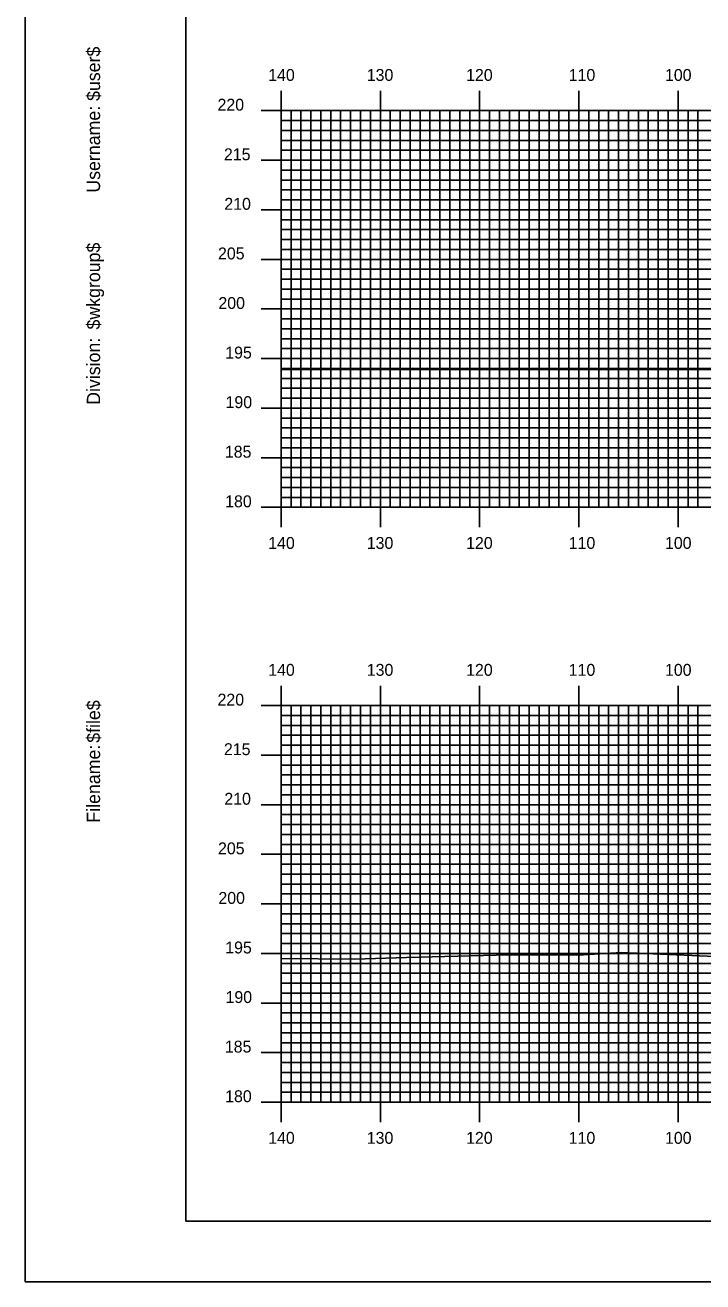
# Model space of a CAD drawing. Extents: x 1812948 to 1813291, y 442591 to 442811.
# Drawn here: x 1812947.7 to 1813016, y 442590.5 to 442717.3 of the extents above; entities that cross this region are included whole.
import ezdxf

# ---------------------------------------------------------------- set-up
doc = ezdxf.new("R2010")
doc.units = 0
for name, color, linetype in [('BORDER', 7, 'Continuous'), ('H_V ANNOTATION', 7, 'Continuous'), ('MAJOR', 7, 'Continuous'), ('MINOR', 7, 'Continuous'), ('PLOT BOUNDARY', 7, 'Continuous'), ('S_Roadway_Centerline', 7, 'Continuous')]:
    doc.layers.add(name, color=color, linetype=linetype)

msp = doc.modelspace()

# ---------------------------------------------------------------- linework, layer by layer
at = {"layer": 'BORDER'}
msp.add_lwpolyline([(1812963.86, 442596.67), (1813283.86, 442596.67), (1813283.86, 442806.67), (1812963.86, 442806.67)], close=True, dxfattribs=at)
at = {"layer": 'MAJOR'}
for p, q in [((1812973.46, 442710.67), (1812973.46, 442708.67)), ((1812983.46, 442710.67), (1812983.46, 442708.67)), ((1812993.46, 442710.67), (1812993.46, 442708.67)), ((1813003.46, 442710.67), (1813003.46, 442708.67)), ((1813013.46, 442710.67), (1813013.46, 442708.67)), ((1812971.45, 442708.67), (1812973.46, 442708.67)), ((1812973.46, 442708.67), (1813253.46, 442708.67)), ((1812973.46, 442668.67), (1812973.46, 442708.67)), ((1812973.46, 442668.67), (1812973.46, 442708.67)), ((1812973.46, 442708.67), (1813253.46, 442708.67)), ((1812983.46, 442668.67), (1812983.46, 442708.67)), ((1812993.46, 442668.67), (1812993.46, 442708.67)), ((1813003.46, 442668.67), (1813003.46, 442708.67)), ((1813013.46, 442668.67), (1813013.46, 442708.67)), ((1812971.45, 442703.67), (1812973.46, 442703.67)), ((1812973.46, 442703.67), (1813253.46, 442703.67)), ((1812971.45, 442698.67), (1812973.46, 442698.67)), ((1812973.46, 442698.67), (1813253.46, 442698.67)), ((1812971.45, 442693.67), (1812973.46, 442693.67)), ((1812973.46, 442693.67), (1813253.46, 442693.67)), ((1812971.45, 442688.67), (1812973.46, 442688.67)), ((1812973.46, 442688.67), (1813253.46, 442688.67)), ((1812971.45, 442683.67), (1812973.46, 442683.67)), ((1812973.46, 442683.67), (1813253.46, 442683.67)), ((1812971.45, 442678.67), (1812973.46, 442678.67)), ((1812973.46, 442678.67), (1813253.46, 442678.67)), ((1812971.45, 442673.67), (1812973.46, 442673.67)), ((1812973.46, 442673.67), (1813253.46, 442673.67)), ((1812971.45, 442668.67), (1812973.46, 442668.67)), ((1812973.46, 442668.67), (1813253.46, 442668.67)), ((1812973.46, 442668.67), (1813253.46, 442668.67)), ((1812973.46, 442666.66), (1812973.46, 442668.67)), ((1812983.46, 442666.66), (1812983.46, 442668.67)), ((1812993.46, 442666.66), (1812993.46, 442668.67)), ((1813003.46, 442666.66), (1813003.46, 442668.67)), ((1813013.46, 442666.66), (1813013.46, 442668.67)), ((1812973.46, 442650.67), (1812973.46, 442648.67)), ((1812983.46, 442650.67), (1812983.46, 442648.67)), ((1812993.46, 442650.67), (1812993.46, 442648.67)), ((1813003.46, 442650.67), (1813003.46, 442648.67)), ((1813013.46, 442650.67), (1813013.46, 442648.67)), ((1812971.45, 442648.67), (1812973.46, 442648.67)), ((1812973.46, 442648.67), (1813253.46, 442648.67)), ((1812973.46, 442608.67), (1812973.46, 442648.67)), ((1812973.46, 442608.67), (1812973.46, 442648.67)), ((1812973.46, 442648.67), (1813253.46, 442648.67)), ((1812983.46, 442608.67), (1812983.46, 442648.67)), ((1812993.46, 442608.67), (1812993.46, 442648.67)), ((1813003.46, 442608.67), (1813003.46, 442648.67)), ((1813013.46, 442608.67), (1813013.46, 442648.67)), ((1812971.45, 442643.67), (1812973.46, 442643.67)), ((1812973.46, 442643.67), (1813253.46, 442643.67)), ((1812971.45, 442638.67), (1812973.46, 442638.67)), ((1812973.46, 442638.67), (1813253.46, 442638.67)), ((1812971.45, 442633.67), (1812973.46, 442633.67)), ((1812973.46, 442633.67), (1813253.46, 442633.67)), ((1812971.45, 442628.67), (1812973.46, 442628.67)), ((1812973.46, 442628.67), (1813253.46, 442628.67)), ((1812971.45, 442623.67), (1812973.46, 442623.67)), ((1812973.46, 442623.67), (1813253.46, 442623.67)), ((1812971.45, 442618.67), (1812973.46, 442618.67)), ((1812973.46, 442618.67), (1813253.46, 442618.67)), ((1812971.45, 442613.67), (1812973.46, 442613.67)), ((1812973.46, 442613.67), (1813253.46, 442613.67)), ((1812971.45, 442608.67), (1812973.46, 442608.67)), ((1812973.46, 442608.67), (1813253.46, 442608.67)), ((1812973.46, 442608.67), (1813253.46, 442608.67)), ((1812973.46, 442606.66), (1812973.46, 442608.67)), ((1812983.46, 442606.66), (1812983.46, 442608.67)), ((1812993.46, 442606.66), (1812993.46, 442608.67)), ((1813003.46, 442606.66), (1813003.46, 442608.67)), ((1813013.46, 442606.66), (1813013.46, 442608.67))]:
    msp.add_line(p, q, dxfattribs=at)
at = {"layer": 'MINOR'}
for p, q in [((1812974.46, 442668.67), (1812974.46, 442708.67)), ((1812975.46, 442668.67), (1812975.46, 442708.67)), ((1812976.46, 442668.67), (1812976.46, 442708.67)), ((1812977.46, 442668.67), (1812977.46, 442708.67)), ((1812978.46, 442668.67), (1812978.46, 442708.67)), ((1812979.46, 442668.67), (1812979.46, 442708.67)), ((1812980.46, 442668.67), (1812980.46, 442708.67)), ((1812981.46, 442668.67), (1812981.46, 442708.67)), ((1812982.46, 442668.67), (1812982.46, 442708.67)), ((1812984.46, 442668.67), (1812984.46, 442708.67)), ((1812985.46, 442668.67), (1812985.46, 442708.67)), ((1812986.46, 442668.67), (1812986.46, 442708.67)), ((1812987.46, 442668.67), (1812987.46, 442708.67)), ((1812988.46, 442668.67), (1812988.46, 442708.67)), ((1812989.46, 442668.67), (1812989.46, 442708.67)), ((1812990.46, 442668.67), (1812990.46, 442708.67)), ((1812991.46, 442668.67), (1812991.46, 442708.67)), ((1812992.46, 442668.67), (1812992.46, 442708.67)), ((1812994.46, 442668.67), (1812994.46, 442708.67)), ((1812995.46, 442668.67), (1812995.46, 442708.67)), ((1812996.46, 442668.67), (1812996.46, 442708.67)), ((1812997.46, 442668.67), (1812997.46, 442708.67)), ((1812998.46, 442668.67), (1812998.46, 442708.67)), ((1812999.46, 442668.67), (1812999.46, 442708.67)), ((1813000.46, 442668.67), (1813000.46, 442708.67)), ((1813001.46, 442668.67), (1813001.46, 442708.67)), ((1813002.46, 442668.67), (1813002.46, 442708.67)), ((1813004.46, 442668.67), (1813004.46, 442708.67)), ((1813005.46, 442668.67), (1813005.46, 442708.67)), ((1813006.46, 442668.67), (1813006.46, 442708.67)), ((1813007.46, 442668.67), (1813007.46, 442708.67)), ((1813008.46, 442668.67), (1813008.46, 442708.67)), ((1813009.46, 442668.67), (1813009.46, 442708.67)), ((1813010.46, 442668.67), (1813010.46, 442708.67)), ((1813011.46, 442668.67), (1813011.46, 442708.67)), ((1813012.46, 442668.67), (1813012.46, 442708.67)), ((1813014.46, 442668.67), (1813014.46, 442708.67)), ((1813015.46, 442668.67), (1813015.46, 442708.67)), ((1812973.46, 442707.67), (1813253.46, 442707.67)), ((1812973.46, 442707.67), (1812975.46, 442707.67)), ((1812973.46, 442706.67), (1813253.46, 442706.67)), ((1812973.46, 442706.67), (1812975.46, 442706.67)), ((1812973.46, 442705.67), (1813253.46, 442705.67)), ((1812973.46, 442705.67), (1812975.46, 442705.67)), ((1812973.46, 442704.67), (1813253.46, 442704.67)), ((1812973.46, 442704.67), (1812975.46, 442704.67)), ((1812973.46, 442702.67), (1813253.46, 442702.67)), ((1812973.46, 442702.67), (1812975.46, 442702.67)), ((1812973.46, 442701.67), (1813253.46, 442701.67)), ((1812973.46, 442701.67), (1812975.46, 442701.67)), ((1812973.46, 442700.67), (1813253.46, 442700.67)), ((1812973.46, 442700.67), (1812975.46, 442700.67)), ((1812973.46, 442699.67), (1813253.46, 442699.67)), ((1812973.46, 442699.67), (1812975.46, 442699.67)), ((1812973.46, 442697.67), (1813253.46, 442697.67)), ((1812973.46, 442697.67), (1812975.46, 442697.67)), ((1812973.46, 442696.67), (1813253.46, 442696.67)), ((1812973.46, 442696.67), (1812975.46, 442696.67)), ((1812973.46, 442695.67), (1813253.46, 442695.67)), ((1812973.46, 442695.67), (1812975.46, 442695.67)), ((1812973.46, 442694.67), (1813253.46, 442694.67)), ((1812973.46, 442694.67), (1812975.46, 442694.67)), ((1812973.46, 442692.67), (1813253.46, 442692.67)), ((1812973.46, 442692.67), (1812975.46, 442692.67)), ((1812973.46, 442691.67), (1813253.46, 442691.67)), ((1812973.46, 442691.67), (1812975.46, 442691.67)), ((1812973.46, 442690.67), (1813253.46, 442690.67)), ((1812973.46, 442690.67), (1812975.46, 442690.67)), ((1812973.46, 442689.67), (1813253.46, 442689.67)), ((1812973.46, 442689.67), (1812975.46, 442689.67)), ((1812973.46, 442687.67), (1813253.46, 442687.67)), ((1812973.46, 442687.67), (1812975.46, 442687.67)), ((1812973.46, 442686.67), (1813253.46, 442686.67)), ((1812973.46, 442686.67), (1812975.46, 442686.67)), ((1812973.46, 442685.67), (1813253.46, 442685.67)), ((1812973.46, 442685.67), (1812975.46, 442685.67)), ((1812973.46, 442684.67), (1813253.46, 442684.67)), ((1812973.46, 442684.67), (1812975.46, 442684.67)), ((1812973.46, 442682.67), (1813253.46, 442682.67)), ((1812973.46, 442682.67), (1812975.46, 442682.67)), ((1812973.46, 442681.67), (1813253.46, 442681.67)), ((1812973.46, 442681.67), (1812975.46, 442681.67)), ((1812973.46, 442680.67), (1813253.46, 442680.67)), ((1812973.46, 442680.67), (1812975.46, 442680.67)), ((1812973.46, 442679.67), (1813253.46, 442679.67)), ((1812973.46, 442679.67), (1812975.46, 442679.67)), ((1812973.46, 442677.67), (1813253.46, 442677.67)), ((1812973.46, 442677.67), (1812975.46, 442677.67)), ((1812973.46, 442676.67), (1813253.46, 442676.67)), ((1812973.46, 442676.67), (1812975.46, 442676.67)), ((1812973.46, 442675.67), (1813253.46, 442675.67)), ((1812973.46, 442675.67), (1812975.46, 442675.67)), ((1812973.46, 442674.67), (1813253.46, 442674.67)), ((1812973.46, 442674.67), (1812975.46, 442674.67)), ((1812973.46, 442672.67), (1813253.46, 442672.67)), ((1812973.46, 442672.67), (1812975.46, 442672.67)), ((1812973.46, 442671.67), (1813253.46, 442671.67)), ((1812973.46, 442671.67), (1812975.46, 442671.67)), ((1812973.46, 442670.67), (1813253.46, 442670.67)), ((1812973.46, 442670.67), (1812975.46, 442670.67)), ((1812973.46, 442669.67), (1813253.46, 442669.67)), ((1812973.46, 442669.67), (1812975.46, 442669.67)), ((1812974.46, 442608.67), (1812974.46, 442648.67)), ((1812975.46, 442608.67), (1812975.46, 442648.67)), ((1812976.46, 442608.67), (1812976.46, 442648.67)), ((1812977.46, 442608.67), (1812977.46, 442648.67)), ((1812978.46, 442608.67), (1812978.46, 442648.67)), ((1812979.46, 442608.67), (1812979.46, 442648.67)), ((1812980.46, 442608.67), (1812980.46, 442648.67)), ((1812981.46, 442608.67), (1812981.46, 442648.67)), ((1812982.46, 442608.67), (1812982.46, 442648.67)), ((1812984.46, 442608.67), (1812984.46, 442648.67)), ((1812985.46, 442608.67), (1812985.46, 442648.67)), ((1812986.46, 442608.67), (1812986.46, 442648.67)), ((1812987.46, 442608.67), (1812987.46, 442648.67)), ((1812988.46, 442608.67), (1812988.46, 442648.67)), ((1812989.46, 442608.67), (1812989.46, 442648.67)), ((1812990.46, 442608.67), (1812990.46, 442648.67)), ((1812991.46, 442608.67), (1812991.46, 442648.67)), ((1812992.46, 442608.67), (1812992.46, 442648.67)), ((1812994.46, 442608.67), (1812994.46, 442648.67)), ((1812995.46, 442608.67), (1812995.46, 442648.67)), ((1812996.46, 442608.67), (1812996.46, 442648.67)), ((1812997.46, 442608.67), (1812997.46, 442648.67)), ((1812998.46, 442608.67), (1812998.46, 442648.67)), ((1812999.46, 442608.67), (1812999.46, 442648.67)), ((1813000.46, 442608.67), (1813000.46, 442648.67)), ((1813001.46, 442608.67), (1813001.46, 442648.67)), ((1813002.46, 442608.67), (1813002.46, 442648.67)), ((1813004.46, 442608.67), (1813004.46, 442648.67)), ((1813005.46, 442608.67), (1813005.46, 442648.67)), ((1813006.46, 442608.67), (1813006.46, 442648.67)), ((1813007.46, 442608.67), (1813007.46, 442648.67)), ((1813008.46, 442608.67), (1813008.46, 442648.67)), ((1813009.46, 442608.67), (1813009.46, 442648.67)), ((1813010.46, 442608.67), (1813010.46, 442648.67)), ((1813011.46, 442608.67), (1813011.46, 442648.67)), ((1813012.46, 442608.67), (1813012.46, 442648.67)), ((1813014.46, 442608.67), (1813014.46, 442648.67)), ((1813015.46, 442608.67), (1813015.46, 442648.67)), ((1812973.46, 442647.67), (1813253.46, 442647.67)), ((1812973.46, 442647.67), (1812975.46, 442647.67)), ((1812973.46, 442646.67), (1813253.46, 442646.67)), ((1812973.46, 442646.67), (1812975.46, 442646.67)), ((1812973.46, 442645.67), (1813253.46, 442645.67)), ((1812973.46, 442645.67), (1812975.46, 442645.67)), ((1812973.46, 442644.67), (1813253.46, 442644.67)), ((1812973.46, 442644.67), (1812975.46, 442644.67)), ((1812973.46, 442642.67), (1813253.46, 442642.67)), ((1812973.46, 442642.67), (1812975.46, 442642.67)), ((1812973.46, 442641.67), (1813253.46, 442641.67)), ((1812973.46, 442641.67), (1812975.46, 442641.67)), ((1812973.46, 442640.67), (1813253.46, 442640.67)), ((1812973.46, 442640.67), (1812975.46, 442640.67)), ((1812973.46, 442639.67), (1813253.46, 442639.67)), ((1812973.46, 442639.67), (1812975.46, 442639.67)), ((1812973.46, 442637.67), (1813253.46, 442637.67)), ((1812973.46, 442637.67), (1812975.46, 442637.67)), ((1812973.46, 442636.67), (1813253.46, 442636.67)), ((1812973.46, 442636.67), (1812975.46, 442636.67)), ((1812973.46, 442635.67), (1813253.46, 442635.67)), ((1812973.46, 442635.67), (1812975.46, 442635.67)), ((1812973.46, 442634.67), (1813253.46, 442634.67)), ((1812973.46, 442634.67), (1812975.46, 442634.67)), ((1812973.46, 442632.67), (1813253.46, 442632.67)), ((1812973.46, 442632.67), (1812975.46, 442632.67)), ((1812973.46, 442631.67), (1813253.46, 442631.67)), ((1812973.46, 442631.67), (1812975.46, 442631.67)), ((1812973.46, 442630.67), (1813253.46, 442630.67)), ((1812973.46, 442630.67), (1812975.46, 442630.67)), ((1812973.46, 442629.67), (1813253.46, 442629.67)), ((1812973.46, 442629.67), (1812975.46, 442629.67)), ((1812973.46, 442627.67), (1813253.46, 442627.67)), ((1812973.46, 442627.67), (1812975.46, 442627.67)), ((1812973.46, 442626.67), (1813253.46, 442626.67)), ((1812973.46, 442626.67), (1812975.46, 442626.67)), ((1812973.46, 442625.67), (1813253.46, 442625.67)), ((1812973.46, 442625.67), (1812975.46, 442625.67)), ((1812973.46, 442624.67), (1813253.46, 442624.67)), ((1812973.46, 442624.67), (1812975.46, 442624.67)), ((1812973.46, 442622.67), (1813253.46, 442622.67)), ((1812973.46, 442622.67), (1812975.46, 442622.67)), ((1812973.46, 442621.67), (1813253.46, 442621.67)), ((1812973.46, 442621.67), (1812975.46, 442621.67)), ((1812973.46, 442620.67), (1813253.46, 442620.67)), ((1812973.46, 442620.67), (1812975.46, 442620.67)), ((1812973.46, 442619.67), (1813253.46, 442619.67)), ((1812973.46, 442619.67), (1812975.46, 442619.67)), ((1812973.46, 442617.67), (1813253.46, 442617.67)), ((1812973.46, 442617.67), (1812975.46, 442617.67)), ((1812973.46, 442616.67), (1813253.46, 442616.67)), ((1812973.46, 442616.67), (1812975.46, 442616.67)), ((1812973.46, 442615.67), (1813253.46, 442615.67)), ((1812973.46, 442615.67), (1812975.46, 442615.67)), ((1812973.46, 442614.67), (1813253.46, 442614.67)), ((1812973.46, 442614.67), (1812975.46, 442614.67)), ((1812973.46, 442612.67), (1813253.46, 442612.67)), ((1812973.46, 442612.67), (1812975.46, 442612.67)), ((1812973.46, 442611.67), (1813253.46, 442611.67)), ((1812973.46, 442611.67), (1812975.46, 442611.67)), ((1812973.46, 442610.67), (1813253.46, 442610.67)), ((1812973.46, 442610.67), (1812975.46, 442610.67)), ((1812973.46, 442609.67), (1813253.46, 442609.67)), ((1812973.46, 442609.67), (1812975.46, 442609.67))]:
    msp.add_line(p, q, dxfattribs=at)
at = {"layer": 'PLOT BOUNDARY'}
msp.add_lwpolyline([(1812947.67, 442590.55), (1813287.67, 442590.55), (1813287.67, 442810.55), (1812947.67, 442810.55)], close=True, dxfattribs=at)
at = {"layer": 'S_Roadway_Centerline'}
for points in [[(1812973.46, 442682.57), (1812976.62, 442682.58), (1812983.23, 442682.57), (1812991.08, 442682.52), (1813001.06, 442682.56), (1813016.82, 442682.57)], [(1812973.46, 442623.16), (1812980.9, 442623.08), (1812986.1, 442623.27), (1812995.12, 442623.51), (1813003.93, 442623.53), (1813007.77, 442623.77), (1813020.36, 442623.24), (1813023.13, 442623.27), (1813026.47, 442623.33), (1813037.42, 442623.38), (1813043.3, 442623.32), (1813054.92, 442623.1), (1813065.77, 442621.86), (1813073.47, 442621.26), (1813084.84, 442620.64), (1813088.36, 442620.5)]]:
    msp.add_lwpolyline(points, dxfattribs=at)

# ---------------------------------------------------------------- texts
at = {"layer": 'BORDER'}
for s, p in [('$user$', (1812955.22, 442709.65)), ('Username:', (1812955.22, 442700.4)), ('$wkgroup$', (1812955.22, 442686.6)), ('Division:', (1812955.22, 442679)), ('$file$', (1812955.22, 442644.92)), ('Filename:', (1812955.22, 442636.86))]:
    msp.add_text(s, height=1.339, rotation=90, dxfattribs=at).set_placement(p)
at = {"layer": 'H_V ANNOTATION'}
for s, p in [('140', (1812972.16, 442711.67)), ('130', (1812982.09, 442711.67)), ('120', (1812992.1, 442711.67)), ('110', (1813002.44, 442711.67)), ('100', (1813012.14, 442711.67)), ('220', (1812967.05, 442708.67)), ('215', (1812967.7, 442703.67)), ('210', (1812967.74, 442698.67)), ('205', (1812967.1, 442693.67)), ('200', (1812967.14, 442688.67)), ('195', (1812967.83, 442683.67)), ('190', (1812967.86, 442678.67)), ('185', (1812967.79, 442673.67)), ('180', (1812967.82, 442668.67)), ('140', (1812972.16, 442664.47)), ('130', (1812982.09, 442664.47)), ('120', (1812992.1, 442664.47)), ('110', (1813002.44, 442664.47)), ('100', (1813012.14, 442664.47)), ('140', (1812972.16, 442651.67)), ('130', (1812982.09, 442651.67)), ('120', (1812992.1, 442651.67)), ('110', (1813002.44, 442651.67)), ('100', (1813012.14, 442651.67)), ('220', (1812967.05, 442648.67)), ('215', (1812967.7, 442643.67)), ('210', (1812967.74, 442638.67)), ('205', (1812967.1, 442633.67)), ('200', (1812967.14, 442628.67)), ('195', (1812967.83, 442623.67)), ('190', (1812967.86, 442618.67)), ('185', (1812967.79, 442613.67)), ('180', (1812967.82, 442608.67)), ('140', (1812972.16, 442604.47)), ('130', (1812982.09, 442604.47)), ('120', (1812992.1, 442604.47)), ('110', (1813002.44, 442604.47)), ('100', (1813012.14, 442604.47))]:
    msp.add_text(s, height=1.2, dxfattribs=at).set_placement(p)
at = {"layer": 'MAJOR'}
for p in [(1812973.45, 442668.67), (1812973.45, 442608.67)]:
    msp.add_text('-', height=0.012, dxfattribs=at).set_placement(p)

doc.saveas('drawing.dxf')
